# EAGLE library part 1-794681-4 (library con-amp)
Micro MATE-N-LOK Connectors grid 1.5mm Dual Row Through Hole Vertical Metal Through Hole Holddowns Source: ENG_CD_794681_E.pdf
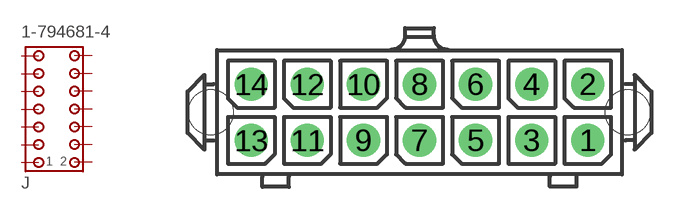
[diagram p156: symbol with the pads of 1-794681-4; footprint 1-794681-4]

Designator prefix J

## 1-794681-4 (MF: TYCO ELECTRONICS; MPN: 1-794681-4; OC_FARNELL: unknown; OC_NEWARK: 10H3811)  [1-794681-4]
1  1  pas
2  2  pas
3  3  pas
4  4  pas
5  5  pas
6  6  pas
7  7  pas
8  8  pas
9  9  pas
10  10  pas
11  11  pas
12  12  pas
13  13  pas
14  14  pas

## Footprint 1-794681-4 (pad centres in mm)
Micro MATE-N-LOK Connectors grid 1.5mm Dual Row Through Hole Vertical Metal Through Hole Holddowns Source: ENG_CD_794681_E.pdf
drill 1 pad 1.778 round: 1 9,-1.5; 2 9,1.5; 3 6,-1.5; 4 6,1.5; 5 3,-1.5; 6 3,1.5; 7 0,-1.5; 8 0,1.5; 9 -3,-1.5; 10 -3,1.5; 11 -6,-1.5; 12 -6,1.5; 13 -9,-1.5; 14 -9,1.5
hole 2.4 at 11.13,0
hole 2.4 at -11.17,0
